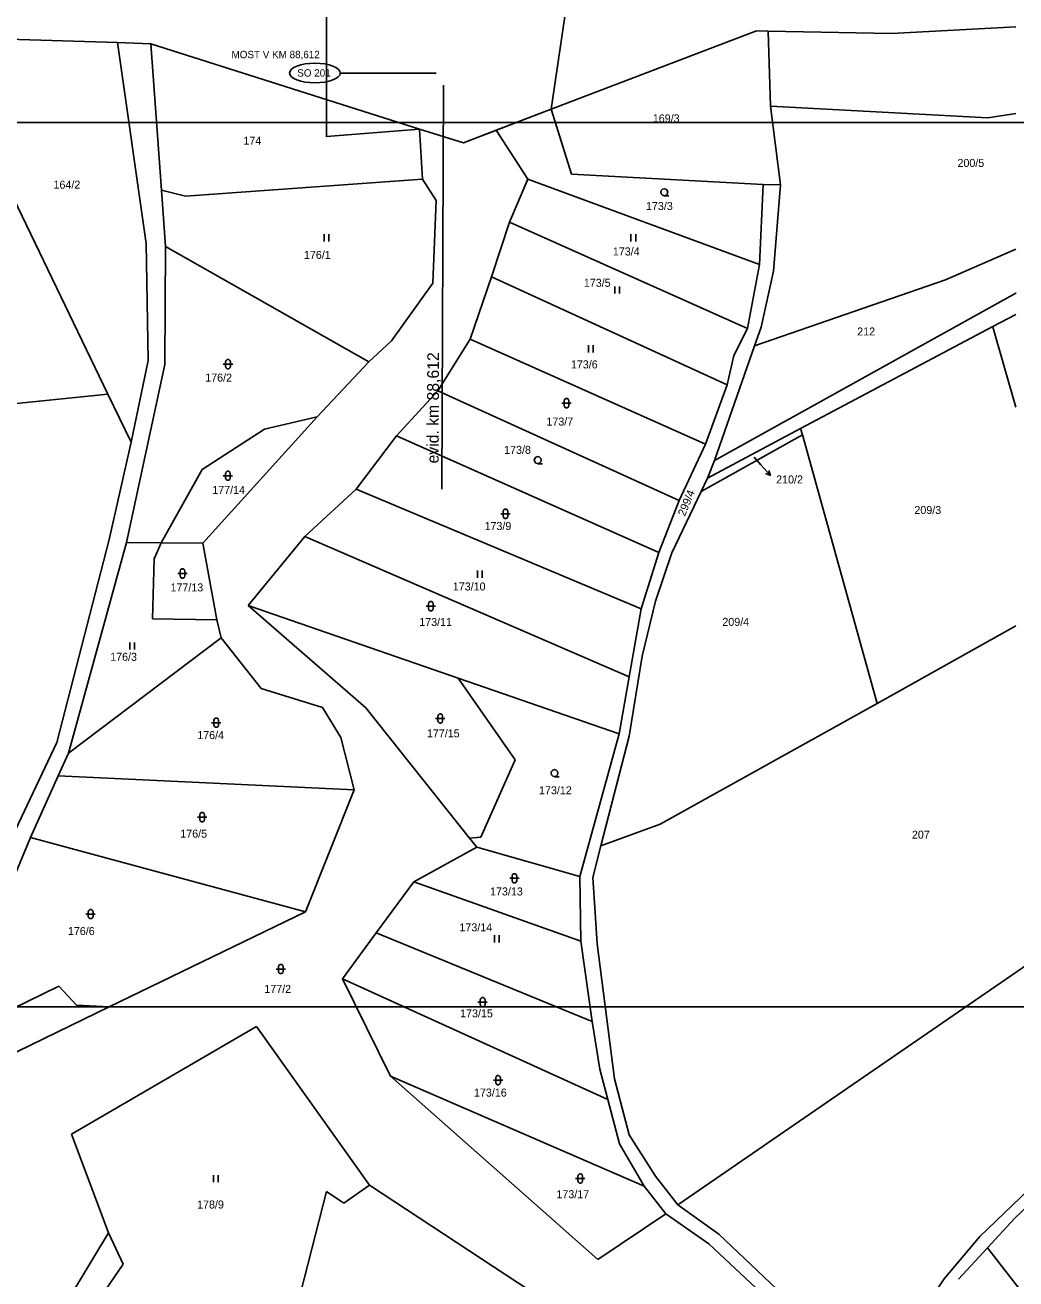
# Model space of a CAD drawing. Extents: x -780000 to -777378, y -1011169 to -1009297.
# Drawn here: x -779319.2 to -779108.8, y -1010745.7 to -1010479.3 of the extents above; entities that cross this region are included whole.
import ezdxf

# ---------------------------------------------------------------- set-up
doc = ezdxf.new("R2010")
doc.units = 0
for name, color, linetype in [('Default', 7, 'Continuous'), ('KLADY_ZMVM', 7, 'Continuous'), ('KN_HRANICE', 7, 'Continuous'), ('KN_KULTURY', 7, 'Continuous'), ('KN_PARCELY', 7, 'Continuous'), ('LEGENDA', 7, 'Continuous'), ('obvod_stavby', 7, 'Continuous'), ('so', 7, 'Continuous'), ('staničení', 7, 'Continuous')]:
    doc.layers.add(name, color=color, linetype=linetype)

# ---------------------------------------------------------------- blocks, each defined once
blk = doc.blocks.new('304')
at = {"layer": 'Default'}
blk.add_lwpolyline([(0, 0), (-0.38, 0.1), (-0.65, 0.37), (-0.75, 0.74), (-0.65, 1.11), (-0.38, 1.38), (-0.01, 1.48), (0.36, 1.38), (0.63, 1.11), (0.73, 0.73), (0.63, 0.35), (0.36, 0.08), (-0.02, -0.02), (0.98, -0.02)], dxfattribs=at)
blk = doc.blocks.new('306')
at = {"layer": 'Default'}
for p, q in [((-0.5, 1.5), (-0.5, 0)), ((0.5, 0), (0.5, 1.5))]:
    blk.add_line(p, q, dxfattribs=at)
blk = doc.blocks.new('316')
at = {"layer": 'Default'}
for points in [[(-1, 1), (0.27, 1), (1, 1)], [(-0.5, 1.5), (-0.4, 1.79), (-0.15, 1.97), (0.16, 1.97), (0.41, 1.79), (0.51, 1.5), (0.51, 0.5), (0.41, 0.21), (0.16, 0.03), (-0.15, 0.03), (-0.4, 0.21), (-0.5, 0.5), (-0.5, 1.5)]]:
    blk.add_lwpolyline(points, dxfattribs=at)
blk = doc.blocks.new('10292')
at = {"layer": 'Default'}
blk.add_line((0, 3), (0, 0), dxfattribs=at)
blk.add_lwpolyline([(-0.5, 2), (0, 3), (0.5, 2)], dxfattribs=at)

msp = doc.modelspace()

# ---------------------------------------------------------------- linework, layer by layer
at = {"layer": 'KLADY_ZMVM'}
for points in [[(-779375, -1010000), (-779375, -1010500), (-779108.78, -1010500)], [(-779108.78, -1010500), (-778750, -1010500), (-778750, -1010000)]]:
    msp.add_lwpolyline(points, dxfattribs=at)
at = {"layer": 'KN_HRANICE'}
for p, q in [((-779207.48, -1010497.19), (-779163.89, -1010480.52)), ((-779163.89, -1010480.52), (-779161.4, -1010480.57)), ((-779161.4, -1010480.57), (-779160.87, -1010496.55)), ((-779161.4, -1010480.57), (-779135.21, -1010481.09)), ((-779135.21, -1010481.09), (-779108.78, -1010479.68)), ((-779299.61, -1010483.03), (-779328.3, -1010482.13)), ((-779292.52, -1010483.32), (-779299.61, -1010483.03)), ((-779299.61, -1010483.03), (-779293.5, -1010525.69)), ((-779292.52, -1010483.32), (-779290.27, -1010514.35)), ((-779292.52, -1010483.32), (-779235.46, -1010501.42)), ((-779219.15, -1010501.65), (-779207.48, -1010497.19)), ((-779207.48, -1010497.19), (-779203.19, -1010510.98)), ((-779160.87, -1010496.55), (-779158.79, -1010513.22)), ((-779160.87, -1010496.55), (-779114.77, -1010499.04)), ((-779114.77, -1010499.04), (-779108.78, -1010498.11)), ((-779235.46, -1010501.42), (-779234.79, -1010512.03)), ((-779235.46, -1010501.42), (-779226.1, -1010504.31)), ((-779226.1, -1010504.31), (-779219.15, -1010501.65)), ((-779212.41, -1010512.04), (-779219.15, -1010501.65)), ((-779301.63, -1010557.72), (-779323.42, -1010512.4)), ((-779234.79, -1010512.03), (-779285.14, -1010515.63)), ((-779234.79, -1010512.03), (-779231.92, -1010516.57)), ((-779212.41, -1010512.04), (-779216.37, -1010521.17)), ((-779212.41, -1010512.04), (-779163.24, -1010530.16)), ((-779203.19, -1010510.98), (-779162.49, -1010513.2)), ((-779162.49, -1010513.2), (-779163.24, -1010530.16)), ((-779162.49, -1010513.2), (-779158.79, -1010513.22)), ((-779158.79, -1010513.22), (-779160.29, -1010531.61)), ((-779290.27, -1010514.35), (-779285.14, -1010515.63)), ((-779290.27, -1010514.35), (-779289.37, -1010526.33)), ((-779231.92, -1010516.57), (-779232.59, -1010534.14)), ((-779216.37, -1010521.17), (-779220.16, -1010532.8)), ((-779216.37, -1010521.17), (-779165.77, -1010543.76)), ((-779293.5, -1010525.69), (-779293.08, -1010550.56)), ((-779289.37, -1010526.33), (-779289.53, -1010551.4)), ((-779246.22, -1010550.88), (-779289.37, -1010526.33)), ((-779123.71, -1010533.43), (-779108.78, -1010526.89)), ((-779163.24, -1010530.16), (-779165.77, -1010543.76)), ((-779160.29, -1010531.61), (-779162.91, -1010543.51)), ((-779232.59, -1010534.14), (-779241.43, -1010546.37)), ((-779220.16, -1010532.8), (-779224.72, -1010546.03)), ((-779220.16, -1010532.8), (-779170.1, -1010555.73)), ((-779164.3, -1010547.48), (-779123.71, -1010533.43)), ((-779108.83, -1010536.25), (-779172.82, -1010571.78)), ((-779108.78, -1010536.22), (-779108.83, -1010536.25)), ((-779113.68, -1010543.36), (-779108.78, -1010540.76)), ((-779165.77, -1010543.76), (-779168.72, -1010549.53)), ((-779162.91, -1010543.51), (-779164.3, -1010547.48)), ((-779154.51, -1010565.04), (-779113.68, -1010543.36)), ((-779113.58, -1010543.69), (-779113.68, -1010543.36)), ((-779108.78, -1010560.46), (-779113.58, -1010543.69)), ((-779246.22, -1010550.88), (-779241.43, -1010546.37)), ((-779224.72, -1010546.03), (-779231.57, -1010557.02)), ((-779224.72, -1010546.03), (-779174.68, -1010568.37)), ((-779164.3, -1010547.48), (-779172.82, -1010571.78)), ((-779293.08, -1010550.56), (-779296.69, -1010567.88)), ((-779168.72, -1010549.53), (-779170.1, -1010555.73)), ((-779289.53, -1010551.4), (-779297.68, -1010589.2)), ((-779257.2, -1010562.56), (-779246.22, -1010550.88)), ((-779170.1, -1010555.73), (-779174.68, -1010568.37)), ((-779389.01, -1010566.7), (-779301.63, -1010557.72)), ((-779296.69, -1010567.88), (-779301.63, -1010557.72)), ((-779231.57, -1010557.02), (-779240.34, -1010566.54)), ((-779231.57, -1010557.02), (-779180.29, -1010580.29)), ((-779281.44, -1010589.38), (-779257.2, -1010562.56)), ((-779268.35, -1010565.14), (-779257.2, -1010562.56)), ((-779281.62, -1010573.71), (-779268.35, -1010565.14)), ((-779240.34, -1010566.54), (-779248.92, -1010577.89)), ((-779240.34, -1010566.54), (-779184.61, -1010591.38)), ((-779154.14, -1010566.37), (-779175.66, -1010578.41)), ((-779174.28, -1010575.54), (-779154.51, -1010565.04)), ((-779154.14, -1010566.37), (-779154.51, -1010565.04)), ((-779138.26, -1010623.45), (-779154.14, -1010566.37)), ((-779296.69, -1010567.88), (-779301.39, -1010588.58)), ((-779174.68, -1010568.37), (-779180.29, -1010580.29)), ((-779172.82, -1010571.78), (-779174.28, -1010575.54)), ((-779290.32, -1010589.28), (-779281.62, -1010573.71)), ((-779174.28, -1010575.54), (-779175.66, -1010578.41)), ((-779248.92, -1010577.89), (-779259.78, -1010587.95)), ((-779248.92, -1010577.89), (-779188.38, -1010603.3)), ((-779175.66, -1010578.41), (-779181.87, -1010591.44)), ((-779180.29, -1010580.29), (-779184.61, -1010591.38)), ((-779301.39, -1010588.58), (-779312.45, -1010631.73)), ((-779297.68, -1010589.2), (-779309.99, -1010633.95)), ((-779297.68, -1010589.2), (-779290.32, -1010589.28)), ((-779290.32, -1010589.28), (-779291.78, -1010592.73)), ((-779290.32, -1010589.28), (-779281.44, -1010589.38)), ((-779278.52, -1010605.68), (-779281.44, -1010589.38)), ((-779259.78, -1010587.95), (-779271.83, -1010602.61)), ((-779259.78, -1010587.95), (-779190.92, -1010617.79)), ((-779291.78, -1010592.73), (-779292.14, -1010605.43)), ((-779184.61, -1010591.38), (-779188.38, -1010603.3)), ((-779181.87, -1010591.44), (-779185.31, -1010601.66)), ((-779271.83, -1010602.61), (-779227.24, -1010618.06)), ((-779271.83, -1010602.61), (-779246.88, -1010624.34)), ((-779188.38, -1010603.3), (-779190.92, -1010617.79)), ((-779188.16, -1010613.35), (-779185.31, -1010601.66)), ((-779292.14, -1010605.43), (-779278.52, -1010605.68)), ((-779278.52, -1010605.68), (-779277.57, -1010609.48)), ((-779138.26, -1010623.45), (-779108.78, -1010606.95)), ((-779277.57, -1010609.48), (-779309.99, -1010633.95)), ((-779277.57, -1010609.48), (-779269.08, -1010620.21)), ((-779190.89, -1010630.38), (-779188.16, -1010613.35)), ((-779227.24, -1010618.06), (-779193.05, -1010629.9)), ((-779227.24, -1010618.06), (-779215.17, -1010635.42)), ((-779190.92, -1010617.79), (-779193.05, -1010629.9)), ((-779269.08, -1010620.21), (-779256.08, -1010624.31)), ((-779256.08, -1010624.31), (-779252.16, -1010630.69)), ((-779246.88, -1010624.34), (-779224.81, -1010652.01)), ((-779184.36, -1010649.06), (-779138.26, -1010623.45)), ((-779193.05, -1010629.9), (-779201.41, -1010660.18)), ((-779196.91, -1010653.64), (-779190.89, -1010630.38)), ((-779312.45, -1010631.73), (-779324.36, -1010656.85)), ((-779252.16, -1010630.69), (-779249.32, -1010641.76)), ((-779309.99, -1010633.95), (-779312.17, -1010638.8)), ((-779215.17, -1010635.42), (-779222.4, -1010651.81)), ((-779312.17, -1010638.8), (-779318.06, -1010651.91)), ((-779312.17, -1010638.8), (-779249.32, -1010641.76)), ((-779249.32, -1010641.76), (-779259.7, -1010667.71)), ((-779196.91, -1010653.64), (-779184.36, -1010649.06)), ((-779222.4, -1010651.81), (-779224.81, -1010652.01)), ((-779318.06, -1010651.91), (-779325.55, -1010669.8)), ((-779318.06, -1010651.91), (-779259.7, -1010667.71)), ((-779236.67, -1010661.34), (-779223.26, -1010653.93)), ((-779224.81, -1010652.01), (-779223.26, -1010653.93)), ((-779223.26, -1010653.93), (-779201.41, -1010660.18)), ((-779198.66, -1010660.39), (-779196.91, -1010653.64)), ((-779236.67, -1010661.34), (-779244.63, -1010672.17)), ((-779236.67, -1010661.34), (-779201.2, -1010673.91)), ((-779201.41, -1010660.18), (-779201.2, -1010673.91)), ((-779198.15, -1010667.92), (-779198.66, -1010660.39)), ((-779259.7, -1010667.71), (-779301.35, -1010687.91)), ((-779197.71, -1010674.51), (-779198.15, -1010667.92)), ((-779244.63, -1010672.17), (-779251.78, -1010681.91)), ((-779244.63, -1010672.17), (-779198.79, -1010690.97)), ((-779201.2, -1010673.91), (-779198.79, -1010690.97)), ((-779194.02, -1010703.17), (-779197.71, -1010674.51)), ((-779180.57, -1010729.93), (-779106.25, -1010678.83)), ((-779330.33, -1010692.44), (-779312.04, -1010683.48)), ((-779312.04, -1010683.48), (-779308.33, -1010687.51)), ((-779251.78, -1010681.91), (-779195.42, -1010707.58)), ((-779251.78, -1010681.91), (-779241.63, -1010702.58)), ((-779301.35, -1010687.91), (-779323.61, -1010698.7)), ((-779308.33, -1010687.51), (-779301.35, -1010687.91)), ((-779198.79, -1010690.97), (-779197.12, -1010701.12)), ((-779309.36, -1010714.92), (-779270.06, -1010692.04)), ((-779270.06, -1010692.04), (-779246.07, -1010725.76)), ((-779197.12, -1010701.12), (-779195.42, -1010707.58)), ((-779197.61, -1010741.55), (-779241.63, -1010702.58)), ((-779241.63, -1010702.58), (-779187.71, -1010725.99)), ((-779190.93, -1010715.06), (-779194.02, -1010703.17)), ((-779195.42, -1010707.58), (-779192.95, -1010716.95)), ((-779309.36, -1010714.92), (-779301.54, -1010735.91)), ((-779185.34, -1010723.85), (-779190.93, -1010715.06)), ((-779192.95, -1010716.95), (-779187.71, -1010725.99)), ((-779095.53, -1010716.56), (-779116.46, -1010736.64)), ((-779109.06, -1010732.81), (-779096.96, -1010721.21)), ((-779251.52, -1010729.6), (-779246.07, -1010725.76)), ((-779246.07, -1010725.76), (-779197.77, -1010757.47)), ((-779187.71, -1010725.99), (-779183.15, -1010731.82)), ((-779180.57, -1010729.93), (-779185.34, -1010723.85)), ((-779255.21, -1010727.12), (-779263.87, -1010760.8)), ((-779255.21, -1010727.12), (-779251.52, -1010729.6)), ((-779171.89, -1010736.2), (-779180.57, -1010729.93)), ((-779197.61, -1010741.55), (-779183.15, -1010731.82)), ((-779183.15, -1010731.82), (-779174.03, -1010738.22)), ((-779114.85, -1010739.08), (-779109.06, -1010732.81)), ((-779312.63, -1010754.3), (-779301.54, -1010735.91)), ((-779301.54, -1010735.91), (-779298.42, -1010742.54)), ((-779138.78, -1010767.46), (-779171.89, -1010736.2)), ((-779116.46, -1010736.64), (-779124.03, -1010745.63)), ((-779174.03, -1010738.22), (-779140.28, -1010769.67)), ((-779121, -1010745.73), (-779114.85, -1010739.08)), ((-779114.85, -1010739.08), (-779044.24, -1010829.34)), ((-779306.77, -1010754.81), (-779298.42, -1010742.54)), ((-779138.78, -1010767.46), (-779124.03, -1010745.63))]:
    msp.add_line(p, q, dxfattribs=at)
at = {"layer": 'KN_PARCELY'}
msp.add_line((-779164.4, -1010571.13), (-779162.94, -1010572.75), dxfattribs=at)
at = {"layer": 'LEGENDA'}
msp.add_lwpolyline([(-779530.66, -1010687.91), (-778936.66, -1010687.91), (-778936.66, -1010267.91), (-779530.66, -1010267.91)], close=True, dxfattribs=at)
at = {"layer": 'obvod_stavby'}
msp.add_lwpolyline([(-779249.69, -1010446.5), (-779249.69, -1010426.74), (-779238.66, -1010426.74), (-779242.1, -1010401.61), (-779239.48, -1010394.92), (-779235.13, -1010426.74), (-779233.15, -1010426.74), (-779223.61, -1010445.86), (-779200.73, -1010455.74), (-779202.13, -1010460.62), (-779207.48, -1010497.19), (-779226.1, -1010504.31), (-779235.46, -1010501.42), (-779255.21, -1010502.98), (-779255.18, -1010446.63), (-779249.69, -1010446.5)], dxfattribs=at)
at = {"layer": 'so'}
msp.add_line((-779252.29, -1010489.49), (-779231.94, -1010489.49), dxfattribs=at)
msp.add_ellipse((-779257.67, -1010489.49), major_axis=(-5.39, 0), ratio=0.386613, dxfattribs=at)
at = {"layer": 'staničení'}
msp.add_line((-779230.74, -1010577.88), (-779230.36, -1010492.07), dxfattribs=at)

# ---------------------------------------------------------------- block references
at = {"layer": 'KN_KULTURY'}
for name, p in [('304', (-779183.45, -1010515.55)), ('306', (-779255.22, -1010525.25)), ('306', (-779190.04, -1010525.25)), ('306', (-779193.5, -1010536.35)), ('306', (-779199.05, -1010548.83)), ('316', (-779276.13, -1010552.33)), ('316', (-779204.25, -1010560.63)), ('304', (-779210.34, -1010572.46)), ('316', (-779276.15, -1010576.04)), ('316', (-779217.18, -1010584.14)), ('316', (-779285.79, -1010596.82)), ('306', (-779222.63, -1010596.7)), ('316', (-779233.06, -1010603.75)), ('306', (-779296.48, -1010611.97)), ('316', (-779278.62, -1010628.51)), ('316', (-779231.05, -1010627.61)), ('304', (-779206.77, -1010638.96)), ('316', (-779281.63, -1010648.57)), ('316', (-779215.3, -1010661.57)), ('316', (-779305.31, -1010669.17)), ('306', (-779219.04, -1010674.18)), ('316', (-779264.9, -1010680.84)), ('316', (-779222.05, -1010687.89)), ('316', (-779218.77, -1010704.46)), ('306', (-779278.73, -1010725.12)), ('316', (-779201.31, -1010725.34))]:
    msp.add_blockref(name, p, dxfattribs=at)
at = {"layer": 'KN_PARCELY', "rotation": -138.03614999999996}
msp.add_blockref('10292', (-779162.94, -1010572.75), dxfattribs=at)

# ---------------------------------------------------------------- texts
at = {"layer": 'KN_PARCELY'}
for s, height, p in [('169/3', 1.7, (-779185.9, -1010499.97)), ('174', 1.7, (-779272.85, -1010504.71)), ('200/5', 1.7, (-779121.19, -1010509.44)), ('164/2', 1.7, (-779313.19, -1010514.06)), ('173/3', 1.7, (-779187.35, -1010518.59)), ('173/4', 1.7, (-779194.39, -1010528.25)), ('176/1', 1.7, (-779260, -1010528.98)), ('173/5', 1.7, (-779200.55, -1010534.9)), ('212', 1.7, (-779142.49, -1010545.25)), ('173/6', 1.7, (-779203.3, -1010552.24)), ('176/2', 1.7, (-779280.97, -1010555.05)), ('173/7', 1.7, (-779208.5, -1010564.38)), ('173/8', 1.7, (-779217.48, -1010570.4)), ('210/2', 0.1, (-779164.39, -1010571.13)), ('177/14', 1.7, (-779279.47, -1010578.91)), ('210/2', 1.7, (-779159.7, -1010576.68)), ('209/3', 1.7, (-779130.34, -1010583.17)), ('173/9', 1.7, (-779221.64, -1010586.58)), ('177/13', 1.7, (-779288.34, -1010599.62)), ('173/10', 1.7, (-779228.38, -1010599.42)), ('173/11', 1.7, (-779235.51, -1010606.96)), ('209/4', 1.7, (-779171.13, -1010606.94)), ('176/3', 1.7, (-779301.15, -1010614.36)), ('176/4', 1.7, (-779282.66, -1010631)), ('177/15', 1.7, (-779233.88, -1010630.62)), ('173/12', 1.7, (-779210.07, -1010642.72)), ('176/5', 1.7, (-779286.26, -1010651.93)), ('207', 1.7, (-779130.87, -1010652.15)), ('173/13', 1.7, (-779220.47, -1010664.21)), ('173/14', 1.7, (-779226.97, -1010671.84)), ('176/6', 1.7, (-779310.13, -1010672.62)), ('177/2', 1.7, (-779268.41, -1010684.92)), ('173/15', 1.7, (-779226.83, -1010690.11)), ('173/16', 1.7, (-779223.88, -1010706.94)), ('178/9', 1.7, (-779282.69, -1010730.72)), ('173/17', 1.7, (-779206.37, -1010728.53))]:
    msp.add_text(s, height=height, dxfattribs=at).set_placement(p)
msp.add_text('299/4', height=1.7, rotation=67.781, dxfattribs=at).set_placement((-779179.08, -1010583.77))
at = {"layer": 'so'}
for s, height, p in [('MOST V KM 88,612', 1.5667, (-779275.38, -1010486.34)), ('SO 201', 1.567, (-779261.42, -1010490.25))]:
    msp.add_text(s, height=height, rotation=360, dxfattribs=at).set_placement(p)
at = {"layer": 'staničení'}
msp.add_text('evid. km 88,612', height=2.5, rotation=89.7477, dxfattribs=at).set_placement((-779231.4, -1010572.43))

doc.saveas('drawing.dxf')
